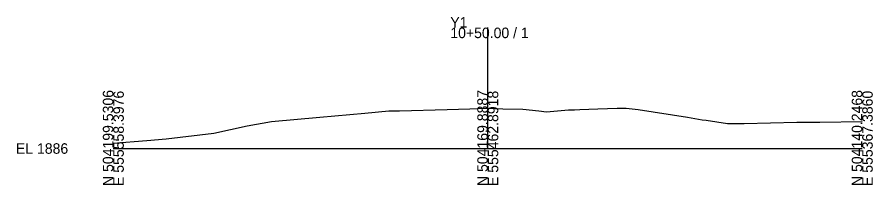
# Model space of a CAD drawing. Extents: x -26 to 203, y -10 to 5015.
# Drawn here: x -25.7 to 202.8, y 490.3 to 535 of the extents above; entities that cross this region are included whole.
import ezdxf

# ---------------------------------------------------------------- set-up
doc = ezdxf.new("R2010")
doc.units = 0
doc.layers.add('Exist Cross Section Cell', color=7, linetype='Continuous')
doc.layers.add('Exist XS Ground Line', color=7, linetype='Continuous')

msp = doc.modelspace()

# ---------------------------------------------------------------- linework, layer by layer
at = {"layer": 'Exist Cross Section Cell'}
for p, q in [((100, 500), (100, 532.24)), ((0, 500), (100, 500)), ((100, 500), (200, 500))]:
    msp.add_line(p, q, dxfattribs=at)
at = {"layer": 'Exist XS Ground Line'}
for p, q in [((67.2, 509.39), (73.61, 510.05)), ((73.61, 510.05), (76.39, 510.05)), ((76.39, 510.05), (89.12, 510.37)), ((89.12, 510.37), (95.17, 510.6)), ((95.17, 510.6), (99.71, 510.74)), ((99.71, 510.74), (104.02, 510.61)), ((104.02, 510.61), (109.37, 510.46)), ((109.37, 510.46), (113.67, 510.08)), ((113.67, 510.08), (115.65, 509.8)), ((115.65, 509.8), (121.57, 510.32)), ((121.57, 510.32), (122.33, 510.32)), ((122.33, 510.32), (123.12, 510.33)), ((123.12, 510.33), (124.6, 510.37)), ((124.6, 510.37), (129.37, 510.55)), ((129.37, 510.55), (134.59, 510.72)), ((134.59, 510.72), (136.92, 510.75)), ((136.92, 510.75), (140.15, 510.37)), ((140.15, 510.37), (153.34, 508.38)), ((42.26, 507.2), (55.14, 508.34)), ((55.14, 508.34), (67.2, 509.39)), ((153.34, 508.38), (157.28, 507.66)), ((157.28, 507.66), (158.36, 507.52)), ((158.36, 507.52), (164.01, 506.66)), ((26.85, 504.05), (35.74, 506.06)), ((35.74, 506.06), (42.26, 507.2)), ((164.01, 506.66), (168.46, 506.69)), ((168.46, 506.69), (182.49, 507.04)), ((182.49, 507.04), (188.7, 507.01)), ((188.7, 507.01), (200, 507.22)), ((14.09, 502.58), (26.85, 504.05)), ((0, 501.41), (8.94, 502.1)), ((8.94, 502.1), (14.09, 502.58))]:
    msp.add_line(p, q, dxfattribs=at)

# ---------------------------------------------------------------- texts
at = {"layer": 'Exist Cross Section Cell'}
for s, p in [('Y1', (90, 532.24)), ('10+50.00 / 1', (90, 529.44)), ('EL 1886', (-26, 498.6))]:
    msp.add_text(s, height=2.8, dxfattribs=at).set_placement(p)
for s, p in [('N 504199.5306', (0, 490)), ('E 555558.3976', (2.8, 490)), ('N 504169.8887', (100, 490)), ('E 555462.8918', (102.8, 490)), ('N 504140.2468', (200, 490)), ('E 555367.3860', (202.8, 490))]:
    msp.add_text(s, height=2.8, rotation=90, dxfattribs=at).set_placement(p)

doc.saveas('drawing.dxf')
